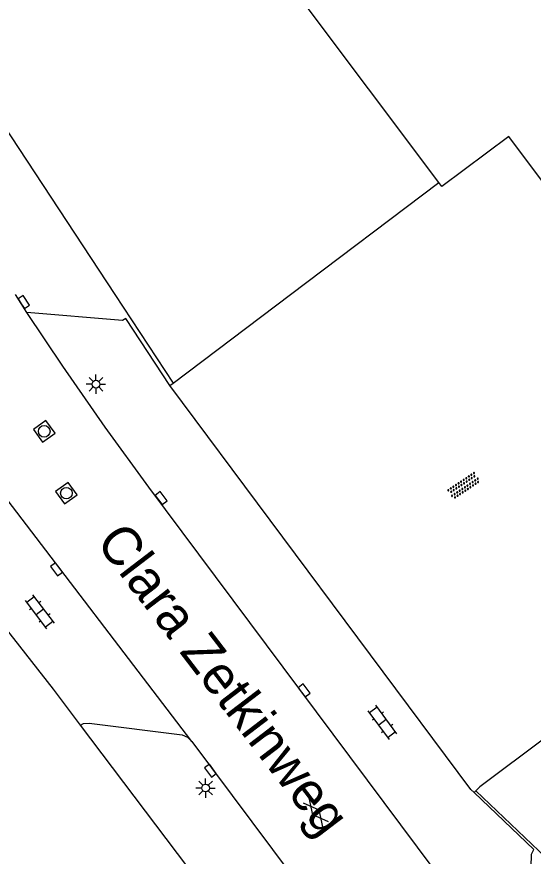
# Model space of a CAD drawing. Extents: x 126000 to 131009, y 393000 to 395500.
# Drawn here: x 130824.5 to 130857.9, y 393963.6 to 394018 of the extents above; entities that cross this region are included whole.
import ezdxf

# ---------------------------------------------------------------- set-up
doc = ezdxf.new("R2010")
doc.units = 0
for name, color, linetype in [('gg-afsc-hekwerk', 7, 'Continuous'), ('gg-anno-openbare ruimte label', 7, 'Continuous'), ('gg-bbg-hoofdgebouw', 7, 'Continuous'), ('gg-knt-verharding', 7, 'Continuous'), ('gt-grn-vlakafsluiter', 7, 'Continuous'), ('gt-symb-gesloten verharding', 7, 'Continuous'), ('gt-symb-klinker verharding', 7, 'Continuous'), ('gt-symb-kolk', 7, 'Continuous'), ('gt-symb-lichtmast', 7, 'Continuous'), ('gt-symb-overige verharding', 7, 'Continuous'), ('gt-symb-rioolschacht', 7, 'Continuous')]:
    doc.layers.add(name, color=color, linetype=linetype)

# ---------------------------------------------------------------- blocks, each defined once
blk = doc.blocks.new('gt0-RS')
at = {"layer": 'gt-symb-rioolschacht'}
blk.add_lwpolyline([(-0.5, -0.5), (0.5, -0.5), (0.5, 0.5), (-0.5, 0.5)], close=True, dxfattribs=at)
blk.add_circle((0, 0), 0.375, dxfattribs=at)
blk = doc.blocks.new('gt0-LMAST')
at = {"layer": 'gt-symb-lichtmast'}
for p, q in [((-0.005, 0.246), (-0.005, 0.621)), ((-0.182, 0.173), (-0.447, 0.438)), ((0.172, 0.173), (0.437, 0.438)), ((-0.255, -0.004), (-0.63, -0.004)), ((-0.182, -0.181), (-0.447, -0.446)), ((-0.005, -0.254), (-0.005, -0.629)), ((0.437, -0.446), (0.172, -0.181)), ((0.245, -0.004), (0.62, -0.004))]:
    blk.add_line(p, q, dxfattribs=at)
blk.add_circle((-0.005, -0.004), 0.25, dxfattribs=at)
blk = doc.blocks.new('gt0-KOLK')
at = {"layer": 'gt-symb-kolk'}
blk.add_lwpolyline([(0, 0), (0.375, 0), (0.375, 0.4), (-0.375, 0.4), (-0.375, 0), (0, 0)], dxfattribs=at)
blk = doc.blocks.new('gt0-KL1')
at = {"layer": 'gt-symb-klinker verharding'}
for p, q in [((-1.15, 0.3), (1.15, 0.3)), ((-1, -0.3), (-1, 0.3)), ((-0.5, 0.3), (-0.5, 0.45)), ((0, -0.3), (0, 0.3)), ((0.5, 0.3), (0.5, 0.45)), ((1, -0.3), (1, 0.3)), ((-1.15, -0.3), (1.15, -0.3)), ((-0.5, -0.45), (-0.5, -0.3)), ((0.5, -0.45), (0.5, -0.3))]:
    blk.add_line(p, q, dxfattribs=at)
blk = doc.blocks.new('gt0-OVH')
at = {"layer": 'gt-symb-overige verharding'}
for points in [[(-0.972, 0.298), (-0.967, 0.308), (-0.965, 0.319), (-0.966, 0.33), (-0.971, 0.34), (-0.978, 0.348), (-0.988, 0.353), (-0.999, 0.355), (-1.01, 0.354), (-1.02, 0.349), (-1.028, 0.342), (-1.033, 0.332), (-1.035, 0.321), (-1.034, 0.31), (-1.029, 0.3), (-1.022, 0.292), (-1.012, 0.287), (-1.001, 0.285), (-0.99, 0.286), (-0.98, 0.291)], [(-0.872, 0.106), (-0.867, 0.116), (-0.865, 0.126), (-0.866, 0.137), (-0.871, 0.147), (-0.878, 0.156), (-0.888, 0.161), (-0.899, 0.163), (-0.91, 0.162), (-0.92, 0.157), (-0.928, 0.15), (-0.933, 0.14), (-0.935, 0.129), (-0.934, 0.118), (-0.929, 0.108), (-0.922, 0.1), (-0.912, 0.095), (-0.901, 0.092), (-0.89, 0.094), (-0.88, 0.098)], [(-0.772, 0.298), (-0.767, 0.308), (-0.765, 0.319), (-0.766, 0.33), (-0.771, 0.34), (-0.778, 0.348), (-0.788, 0.353), (-0.799, 0.355), (-0.81, 0.354), (-0.82, 0.349), (-0.828, 0.342), (-0.833, 0.332), (-0.835, 0.321), (-0.834, 0.31), (-0.829, 0.3), (-0.822, 0.292), (-0.812, 0.287), (-0.801, 0.285), (-0.79, 0.286), (-0.78, 0.291)], [(-0.672, 0.106), (-0.667, 0.116), (-0.665, 0.126), (-0.666, 0.137), (-0.671, 0.147), (-0.678, 0.156), (-0.688, 0.161), (-0.699, 0.163), (-0.71, 0.162), (-0.72, 0.157), (-0.728, 0.15), (-0.733, 0.14), (-0.735, 0.129), (-0.734, 0.118), (-0.729, 0.108), (-0.722, 0.1), (-0.712, 0.095), (-0.701, 0.092), (-0.69, 0.094), (-0.68, 0.098)], [(-0.572, 0.298), (-0.567, 0.308), (-0.565, 0.319), (-0.566, 0.33), (-0.571, 0.34), (-0.578, 0.348), (-0.588, 0.353), (-0.599, 0.355), (-0.61, 0.354), (-0.62, 0.349), (-0.628, 0.342), (-0.633, 0.332), (-0.635, 0.321), (-0.634, 0.31), (-0.629, 0.3), (-0.622, 0.292), (-0.612, 0.287), (-0.601, 0.285), (-0.59, 0.286), (-0.58, 0.291)], [(-0.472, 0.106), (-0.467, 0.116), (-0.465, 0.126), (-0.466, 0.137), (-0.471, 0.147), (-0.478, 0.156), (-0.488, 0.161), (-0.499, 0.163), (-0.51, 0.162), (-0.52, 0.157), (-0.528, 0.15), (-0.533, 0.14), (-0.535, 0.129), (-0.534, 0.118), (-0.529, 0.108), (-0.522, 0.1), (-0.512, 0.095), (-0.501, 0.092), (-0.49, 0.094), (-0.48, 0.098)], [(-0.372, 0.298), (-0.367, 0.308), (-0.365, 0.319), (-0.366, 0.33), (-0.371, 0.34), (-0.378, 0.348), (-0.388, 0.353), (-0.399, 0.355), (-0.41, 0.354), (-0.42, 0.349), (-0.428, 0.342), (-0.433, 0.332), (-0.435, 0.321), (-0.434, 0.31), (-0.429, 0.3), (-0.422, 0.292), (-0.412, 0.287), (-0.401, 0.285), (-0.39, 0.286), (-0.38, 0.291)], [(-0.272, 0.106), (-0.267, 0.116), (-0.265, 0.126), (-0.266, 0.137), (-0.271, 0.147), (-0.278, 0.156), (-0.288, 0.161), (-0.299, 0.163), (-0.31, 0.162), (-0.32, 0.157), (-0.328, 0.15), (-0.333, 0.14), (-0.335, 0.129), (-0.334, 0.118), (-0.329, 0.108), (-0.322, 0.1), (-0.312, 0.095), (-0.301, 0.092), (-0.29, 0.094), (-0.28, 0.098)], [(-0.172, 0.298), (-0.167, 0.308), (-0.165, 0.319), (-0.166, 0.33), (-0.171, 0.34), (-0.178, 0.348), (-0.188, 0.353), (-0.199, 0.355), (-0.21, 0.354), (-0.22, 0.349), (-0.228, 0.342), (-0.233, 0.332), (-0.235, 0.321), (-0.234, 0.31), (-0.229, 0.3), (-0.222, 0.292), (-0.212, 0.287), (-0.201, 0.285), (-0.19, 0.286), (-0.18, 0.291)], [(-0.072, 0.106), (-0.067, 0.116), (-0.065, 0.126), (-0.066, 0.137), (-0.071, 0.147), (-0.078, 0.156), (-0.088, 0.161), (-0.099, 0.163), (-0.11, 0.162), (-0.12, 0.157), (-0.128, 0.15), (-0.133, 0.14), (-0.135, 0.129), (-0.134, 0.118), (-0.129, 0.108), (-0.122, 0.1), (-0.112, 0.095), (-0.101, 0.092), (-0.09, 0.094), (-0.08, 0.098)], [(0.028, 0.298), (0.033, 0.308), (0.035, 0.319), (0.034, 0.33), (0.029, 0.34), (0.022, 0.348), (0.012, 0.353), (0.001, 0.355), (-0.01, 0.354), (-0.02, 0.349), (-0.028, 0.342), (-0.033, 0.332), (-0.035, 0.321), (-0.034, 0.31), (-0.029, 0.3), (-0.022, 0.292), (-0.012, 0.287), (-0.001, 0.285), (0.01, 0.286), (0.02, 0.291)], [(0.128, 0.106), (0.133, 0.116), (0.135, 0.126), (0.134, 0.137), (0.129, 0.147), (0.122, 0.156), (0.112, 0.161), (0.101, 0.163), (0.09, 0.162), (0.08, 0.157), (0.072, 0.15), (0.067, 0.14), (0.065, 0.129), (0.066, 0.118), (0.071, 0.108), (0.078, 0.1), (0.088, 0.095), (0.099, 0.092), (0.11, 0.094), (0.12, 0.098)], [(0.228, 0.298), (0.233, 0.308), (0.235, 0.319), (0.234, 0.33), (0.229, 0.34), (0.222, 0.348), (0.212, 0.353), (0.201, 0.355), (0.19, 0.354), (0.18, 0.349), (0.172, 0.342), (0.167, 0.332), (0.165, 0.321), (0.166, 0.31), (0.171, 0.3), (0.178, 0.292), (0.188, 0.287), (0.199, 0.285), (0.21, 0.286), (0.22, 0.291)], [(0.328, 0.106), (0.333, 0.116), (0.335, 0.126), (0.334, 0.137), (0.329, 0.147), (0.322, 0.156), (0.312, 0.161), (0.301, 0.163), (0.29, 0.162), (0.28, 0.157), (0.272, 0.15), (0.267, 0.14), (0.265, 0.129), (0.266, 0.118), (0.271, 0.108), (0.278, 0.1), (0.288, 0.095), (0.299, 0.092), (0.31, 0.094), (0.32, 0.098)], [(0.428, 0.298), (0.433, 0.308), (0.435, 0.319), (0.434, 0.33), (0.429, 0.34), (0.422, 0.348), (0.412, 0.353), (0.401, 0.355), (0.39, 0.354), (0.38, 0.349), (0.372, 0.342), (0.367, 0.332), (0.365, 0.321), (0.366, 0.31), (0.371, 0.3), (0.378, 0.292), (0.388, 0.287), (0.399, 0.285), (0.41, 0.286), (0.42, 0.291)], [(0.528, 0.106), (0.533, 0.116), (0.535, 0.126), (0.534, 0.137), (0.529, 0.147), (0.522, 0.156), (0.512, 0.161), (0.501, 0.163), (0.49, 0.162), (0.48, 0.157), (0.472, 0.15), (0.467, 0.14), (0.465, 0.129), (0.466, 0.118), (0.471, 0.108), (0.478, 0.1), (0.488, 0.095), (0.499, 0.092), (0.51, 0.094), (0.52, 0.098)], [(0.628, 0.298), (0.633, 0.308), (0.635, 0.319), (0.634, 0.33), (0.629, 0.34), (0.622, 0.348), (0.612, 0.353), (0.601, 0.355), (0.59, 0.354), (0.58, 0.349), (0.572, 0.342), (0.567, 0.332), (0.565, 0.321), (0.566, 0.31), (0.571, 0.3), (0.578, 0.292), (0.588, 0.287), (0.599, 0.285), (0.61, 0.286), (0.62, 0.291)], [(0.728, 0.106), (0.733, 0.116), (0.735, 0.126), (0.734, 0.137), (0.729, 0.147), (0.722, 0.156), (0.712, 0.161), (0.701, 0.163), (0.69, 0.162), (0.68, 0.157), (0.672, 0.15), (0.667, 0.14), (0.665, 0.129), (0.666, 0.118), (0.671, 0.108), (0.678, 0.1), (0.688, 0.095), (0.699, 0.092), (0.71, 0.094), (0.72, 0.098)], [(0.828, 0.298), (0.833, 0.308), (0.835, 0.319), (0.834, 0.33), (0.829, 0.34), (0.822, 0.348), (0.812, 0.353), (0.801, 0.355), (0.79, 0.354), (0.78, 0.349), (0.772, 0.342), (0.767, 0.332), (0.765, 0.321), (0.766, 0.31), (0.771, 0.3), (0.778, 0.292), (0.788, 0.287), (0.799, 0.285), (0.81, 0.286), (0.82, 0.291)], [(0.928, 0.106), (0.933, 0.116), (0.935, 0.126), (0.934, 0.137), (0.929, 0.147), (0.922, 0.156), (0.912, 0.161), (0.901, 0.163), (0.89, 0.162), (0.88, 0.157), (0.872, 0.15), (0.867, 0.14), (0.865, 0.129), (0.866, 0.118), (0.871, 0.108), (0.878, 0.1), (0.888, 0.095), (0.899, 0.092), (0.91, 0.094), (0.92, 0.098)], [(1.028, 0.298), (1.033, 0.308), (1.035, 0.319), (1.034, 0.33), (1.029, 0.34), (1.022, 0.348), (1.012, 0.353), (1.001, 0.355), (0.99, 0.354), (0.98, 0.349), (0.972, 0.342), (0.967, 0.332), (0.965, 0.321), (0.966, 0.31), (0.971, 0.3), (0.978, 0.292), (0.988, 0.287), (0.999, 0.285), (1.01, 0.286), (1.02, 0.291)], [(-0.972, -0.142), (-0.967, -0.132), (-0.965, -0.121), (-0.966, -0.11), (-0.971, -0.1), (-0.978, -0.092), (-0.988, -0.087), (-0.999, -0.085), (-1.01, -0.086), (-1.02, -0.091), (-1.028, -0.098), (-1.033, -0.108), (-1.035, -0.119), (-1.034, -0.13), (-1.029, -0.14), (-1.022, -0.148), (-1.012, -0.153), (-1.001, -0.155), (-0.99, -0.154), (-0.98, -0.149)], [(-0.872, -0.334), (-0.867, -0.324), (-0.865, -0.314), (-0.866, -0.303), (-0.871, -0.293), (-0.878, -0.284), (-0.888, -0.279), (-0.899, -0.277), (-0.91, -0.278), (-0.92, -0.283), (-0.928, -0.29), (-0.933, -0.3), (-0.935, -0.311), (-0.934, -0.322), (-0.929, -0.332), (-0.922, -0.34), (-0.912, -0.345), (-0.901, -0.348), (-0.89, -0.346), (-0.88, -0.342)], [(-0.772, -0.142), (-0.767, -0.132), (-0.765, -0.121), (-0.766, -0.11), (-0.771, -0.1), (-0.778, -0.092), (-0.788, -0.087), (-0.799, -0.085), (-0.81, -0.086), (-0.82, -0.091), (-0.828, -0.098), (-0.833, -0.108), (-0.835, -0.119), (-0.834, -0.13), (-0.829, -0.14), (-0.822, -0.148), (-0.812, -0.153), (-0.801, -0.155), (-0.79, -0.154), (-0.78, -0.149)], [(-0.672, -0.334), (-0.667, -0.324), (-0.665, -0.314), (-0.666, -0.303), (-0.671, -0.293), (-0.678, -0.284), (-0.688, -0.279), (-0.699, -0.277), (-0.71, -0.278), (-0.72, -0.283), (-0.728, -0.29), (-0.733, -0.3), (-0.735, -0.311), (-0.734, -0.322), (-0.729, -0.332), (-0.722, -0.34), (-0.712, -0.345), (-0.701, -0.348), (-0.69, -0.346), (-0.68, -0.342)], [(-0.572, -0.142), (-0.567, -0.132), (-0.565, -0.121), (-0.566, -0.11), (-0.571, -0.1), (-0.578, -0.092), (-0.588, -0.087), (-0.599, -0.085), (-0.61, -0.086), (-0.62, -0.091), (-0.628, -0.098), (-0.633, -0.108), (-0.635, -0.119), (-0.634, -0.13), (-0.629, -0.14), (-0.622, -0.148), (-0.612, -0.153), (-0.601, -0.155), (-0.59, -0.154), (-0.58, -0.149)], [(-0.472, -0.334), (-0.467, -0.324), (-0.465, -0.314), (-0.466, -0.303), (-0.471, -0.293), (-0.478, -0.284), (-0.488, -0.279), (-0.499, -0.277), (-0.51, -0.278), (-0.52, -0.283), (-0.528, -0.29), (-0.533, -0.3), (-0.535, -0.311), (-0.534, -0.322), (-0.529, -0.332), (-0.522, -0.34), (-0.512, -0.345), (-0.501, -0.348), (-0.49, -0.346), (-0.48, -0.342)], [(-0.372, -0.142), (-0.367, -0.132), (-0.365, -0.121), (-0.366, -0.11), (-0.371, -0.1), (-0.378, -0.092), (-0.388, -0.087), (-0.399, -0.085), (-0.41, -0.086), (-0.42, -0.091), (-0.428, -0.098), (-0.433, -0.108), (-0.435, -0.119), (-0.434, -0.13), (-0.429, -0.14), (-0.422, -0.148), (-0.412, -0.153), (-0.401, -0.155), (-0.39, -0.154), (-0.38, -0.149)], [(-0.272, -0.334), (-0.267, -0.324), (-0.265, -0.314), (-0.266, -0.303), (-0.271, -0.293), (-0.278, -0.284), (-0.288, -0.279), (-0.299, -0.277), (-0.31, -0.278), (-0.32, -0.283), (-0.328, -0.29), (-0.333, -0.3), (-0.335, -0.311), (-0.334, -0.322), (-0.329, -0.332), (-0.322, -0.34), (-0.312, -0.345), (-0.301, -0.348), (-0.29, -0.346), (-0.28, -0.342)], [(-0.172, -0.142), (-0.167, -0.132), (-0.165, -0.121), (-0.166, -0.11), (-0.171, -0.1), (-0.178, -0.092), (-0.188, -0.087), (-0.199, -0.085), (-0.21, -0.086), (-0.22, -0.091), (-0.228, -0.098), (-0.233, -0.108), (-0.235, -0.119), (-0.234, -0.13), (-0.229, -0.14), (-0.222, -0.148), (-0.212, -0.153), (-0.201, -0.155), (-0.19, -0.154), (-0.18, -0.149)], [(-0.072, -0.334), (-0.067, -0.324), (-0.065, -0.314), (-0.066, -0.303), (-0.071, -0.293), (-0.078, -0.284), (-0.088, -0.279), (-0.099, -0.277), (-0.11, -0.278), (-0.12, -0.283), (-0.128, -0.29), (-0.133, -0.3), (-0.135, -0.311), (-0.134, -0.322), (-0.129, -0.332), (-0.122, -0.34), (-0.112, -0.345), (-0.101, -0.348), (-0.09, -0.346), (-0.08, -0.342)], [(0.028, -0.142), (0.033, -0.132), (0.035, -0.121), (0.034, -0.11), (0.029, -0.1), (0.022, -0.092), (0.012, -0.087), (0.001, -0.085), (-0.01, -0.086), (-0.02, -0.091), (-0.028, -0.098), (-0.033, -0.108), (-0.035, -0.119), (-0.034, -0.13), (-0.029, -0.14), (-0.022, -0.148), (-0.012, -0.153), (-0.001, -0.155), (0.01, -0.154), (0.02, -0.149)], [(0.128, -0.334), (0.133, -0.324), (0.135, -0.314), (0.134, -0.303), (0.129, -0.293), (0.122, -0.284), (0.112, -0.279), (0.101, -0.277), (0.09, -0.278), (0.08, -0.283), (0.072, -0.29), (0.067, -0.3), (0.065, -0.311), (0.066, -0.322), (0.071, -0.332), (0.078, -0.34), (0.088, -0.345), (0.099, -0.348), (0.11, -0.346), (0.12, -0.342)], [(0.228, -0.142), (0.233, -0.132), (0.235, -0.121), (0.234, -0.11), (0.229, -0.1), (0.222, -0.092), (0.212, -0.087), (0.201, -0.085), (0.19, -0.086), (0.18, -0.091), (0.172, -0.098), (0.167, -0.108), (0.165, -0.119), (0.166, -0.13), (0.171, -0.14), (0.178, -0.148), (0.188, -0.153), (0.199, -0.155), (0.21, -0.154), (0.22, -0.149)], [(0.328, -0.334), (0.333, -0.324), (0.335, -0.314), (0.334, -0.303), (0.329, -0.293), (0.322, -0.284), (0.312, -0.279), (0.301, -0.277), (0.29, -0.278), (0.28, -0.283), (0.272, -0.29), (0.267, -0.3), (0.265, -0.311), (0.266, -0.322), (0.271, -0.332), (0.278, -0.34), (0.288, -0.345), (0.299, -0.348), (0.31, -0.346), (0.32, -0.342)], [(0.428, -0.142), (0.433, -0.132), (0.435, -0.121), (0.434, -0.11), (0.429, -0.1), (0.422, -0.092), (0.412, -0.087), (0.401, -0.085), (0.39, -0.086), (0.38, -0.091), (0.372, -0.098), (0.367, -0.108), (0.365, -0.119), (0.366, -0.13), (0.371, -0.14), (0.378, -0.148), (0.388, -0.153), (0.399, -0.155), (0.41, -0.154), (0.42, -0.149)], [(0.528, -0.334), (0.533, -0.324), (0.535, -0.314), (0.534, -0.303), (0.529, -0.293), (0.522, -0.284), (0.512, -0.279), (0.501, -0.277), (0.49, -0.278), (0.48, -0.283), (0.472, -0.29), (0.467, -0.3), (0.465, -0.311), (0.466, -0.322), (0.471, -0.332), (0.478, -0.34), (0.488, -0.345), (0.499, -0.348), (0.51, -0.346), (0.52, -0.342)], [(0.628, -0.142), (0.633, -0.132), (0.635, -0.121), (0.634, -0.11), (0.629, -0.1), (0.622, -0.092), (0.612, -0.087), (0.601, -0.085), (0.59, -0.086), (0.58, -0.091), (0.572, -0.098), (0.567, -0.108), (0.565, -0.119), (0.566, -0.13), (0.571, -0.14), (0.578, -0.148), (0.588, -0.153), (0.599, -0.155), (0.61, -0.154), (0.62, -0.149)], [(0.728, -0.334), (0.733, -0.324), (0.735, -0.314), (0.734, -0.303), (0.729, -0.293), (0.722, -0.284), (0.712, -0.279), (0.701, -0.277), (0.69, -0.278), (0.68, -0.283), (0.672, -0.29), (0.667, -0.3), (0.665, -0.311), (0.666, -0.322), (0.671, -0.332), (0.678, -0.34), (0.688, -0.345), (0.699, -0.348), (0.71, -0.346), (0.72, -0.342)], [(0.828, -0.142), (0.833, -0.132), (0.835, -0.121), (0.834, -0.11), (0.829, -0.1), (0.822, -0.092), (0.812, -0.087), (0.801, -0.085), (0.79, -0.086), (0.78, -0.091), (0.772, -0.098), (0.767, -0.108), (0.765, -0.119), (0.766, -0.13), (0.771, -0.14), (0.778, -0.148), (0.788, -0.153), (0.799, -0.155), (0.81, -0.154), (0.82, -0.149)], [(0.928, -0.334), (0.933, -0.324), (0.935, -0.314), (0.934, -0.303), (0.929, -0.293), (0.922, -0.284), (0.912, -0.279), (0.901, -0.277), (0.89, -0.278), (0.88, -0.283), (0.872, -0.29), (0.867, -0.3), (0.865, -0.311), (0.866, -0.322), (0.871, -0.332), (0.878, -0.34), (0.888, -0.345), (0.899, -0.348), (0.91, -0.346), (0.92, -0.342)], [(1.028, -0.142), (1.033, -0.132), (1.035, -0.121), (1.034, -0.11), (1.029, -0.1), (1.022, -0.092), (1.012, -0.087), (1.001, -0.085), (0.99, -0.086), (0.98, -0.091), (0.972, -0.098), (0.967, -0.108), (0.965, -0.119), (0.966, -0.13), (0.971, -0.14), (0.978, -0.148), (0.988, -0.153), (0.999, -0.155), (1.01, -0.154), (1.02, -0.149)]]:
    blk.add_lwpolyline(points, close=True, dxfattribs=at)
blk = doc.blocks.new('gt0-GESVH1')
at = {"layer": 'gt-symb-gesloten verharding'}
for p, q in [((-0.992, -0.261), (0.008, 0.239)), ((0.008, -0.261), (-0.992, 0.239)), ((0.008, 0.239), (1.008, -0.261)), ((1.008, 0.239), (0.008, -0.261))]:
    blk.add_line(p, q, dxfattribs=at)

msp = doc.modelspace()

# ---------------------------------------------------------------- linework, layer by layer
at = {"layer": 'gg-afsc-hekwerk'}
for p, q in [((130842.239, 394000), (130851.823, 394007.234)), ((130830.861, 394000), (130834.633, 393994.26)), ((130834.633, 393994.26), (130842.239, 394000)), ((130854.218, 393967.879), (130871.426, 393951.403))]:
    msp.add_line(p, q, dxfattribs=at)
for points in [[(130857.9, 394089.297), (130810.653, 394030.756), (130830.861, 394000)], [(130828.661, 393972.129), (130826.906, 393974.452), (130819.111, 393984.397)], [(130871.537, 393980.923), (130854.468, 393968.126), (130854.218, 393967.879)], [(130848.392, 393904.683), (130863.43, 393926.1), (130828.661, 393972.129)]]:
    msp.add_lwpolyline(points, dxfattribs=at)
at = {"layer": 'gg-bbg-hoofdgebouw'}
for points in [[(130851.823, 394007.234), (130829.084, 394037.568), (130868.321, 394066.988), (130891.005, 394036.713), (130895.074, 394039.762)], [(130871.537, 393980.923), (130871.381, 393981.131), (130875.708, 393984.341), (130856.341, 394010.227), (130852.012, 394006.982), (130851.823, 394007.234)]]:
    msp.add_lwpolyline(points, dxfattribs=at)
at = {"layer": 'gg-knt-verharding'}
for p, q in [((130825.187, 393998.819), (130824.447, 394000)), ((130835.861, 393971.073), (130819.806, 393992.094)), ((130835.861, 393971.073), (130852.559, 393948.642))]:
    msp.add_line(p, q, dxfattribs=at)
for points in [[(130857.636, 393957.079), (130851.526, 393962.776), (130833.062, 393987.532), (130830.248, 393991.415), (130827.516, 393995.356), (130825.187, 393998.819)], [(130834.424, 393994.104), (130831.589, 393998.441), (130831.367, 393998.306), (130825.187, 393998.819)], [(130854.109, 393967.765), (130853.903, 393967.962), (130834.424, 393994.104)], [(130828.661, 393972.129), (130828.848, 393972.237), (130829.22, 393972.264), (130835.227, 393971.497), (130835.58, 393971.339), (130835.861, 393971.073)], [(130857.636, 393957.079), (130857.811, 393963.769), (130857.972, 393964.08), (130854.109, 393967.765)]]:
    msp.add_lwpolyline(points, dxfattribs=at)
at = {"layer": 'gt-grn-vlakafsluiter'}
for p, q in [((130834.424, 393994.104), (130834.633, 393994.26)), ((130854.109, 393967.765), (130854.218, 393967.879))]:
    msp.add_line(p, q, dxfattribs=at)

# ---------------------------------------------------------------- block references
at = {"layer": 'gt-symb-gesloten verharding', "rotation": -51.1701750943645}
msp.add_blockref('gt0-GESVH1', (130843.868, 393966.494), dxfattribs=at)
at = {"layer": 'gt-symb-klinker verharding'}
for p, rotation in [((130826.024, 393979.453), 127.36253068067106), ((130848.185, 393972.308), 126.5834211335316)]:
    msp.add_blockref('gt0-KL1', p, dxfattribs=dict(at, rotation=rotation))
at = {"layer": 'gt-symb-kolk'}
for p, rotation in [((130824.817, 393999.4), -57.50242843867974), ((130833.705, 393986.696), -52.4314079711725), ((130827.261, 393982.333), 127.23665897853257), ((130842.951, 393974.249), -53.416578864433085), ((130837.211, 393969.296), 126.5834211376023)]:
    msp.add_blockref('gt0-KOLK', p, dxfattribs=dict(at, rotation=rotation))
at = {"layer": 'gt-symb-lichtmast'}
for p in [(130829.656, 393994.194), (130836.745, 393968.061)]:
    msp.add_blockref('gt0-LMAST', p, dxfattribs=at)
at = {"layer": 'gt-symb-overige verharding', "rotation": 33.705956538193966}
msp.add_blockref('gt0-OVH', (130853.442, 393987.618), dxfattribs=at)
at = {"layer": 'gt-symb-rioolschacht'}
for p, rotation in [((130826.305, 393991.139), -54.27586519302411), ((130827.739, 393987.135), -54.27586519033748)]:
    msp.add_blockref('gt0-RS', p, dxfattribs=dict(at, rotation=rotation))

# ---------------------------------------------------------------- texts
at = {"layer": 'gg-anno-openbare ruimte label'}
msp.add_text('Clara Zetkinweg', height=2.5, rotation=307.4, dxfattribs=at).set_placement((130829.589, 393983.96))

doc.saveas('drawing.dxf')
